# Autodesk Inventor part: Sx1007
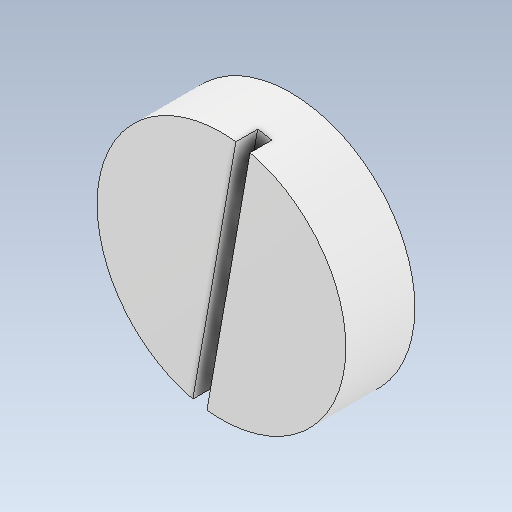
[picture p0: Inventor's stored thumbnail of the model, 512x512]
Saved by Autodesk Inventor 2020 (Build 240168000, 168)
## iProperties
Created: 2021-02
Part Number: Sx1007
Material: Generico
Document SubType Name: Modeling
Designer: zambolin
Density: 1 g/cm^3
Appearance: Default
Author: zambolin
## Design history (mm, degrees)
feature "Solido2"
node "Solido1"
